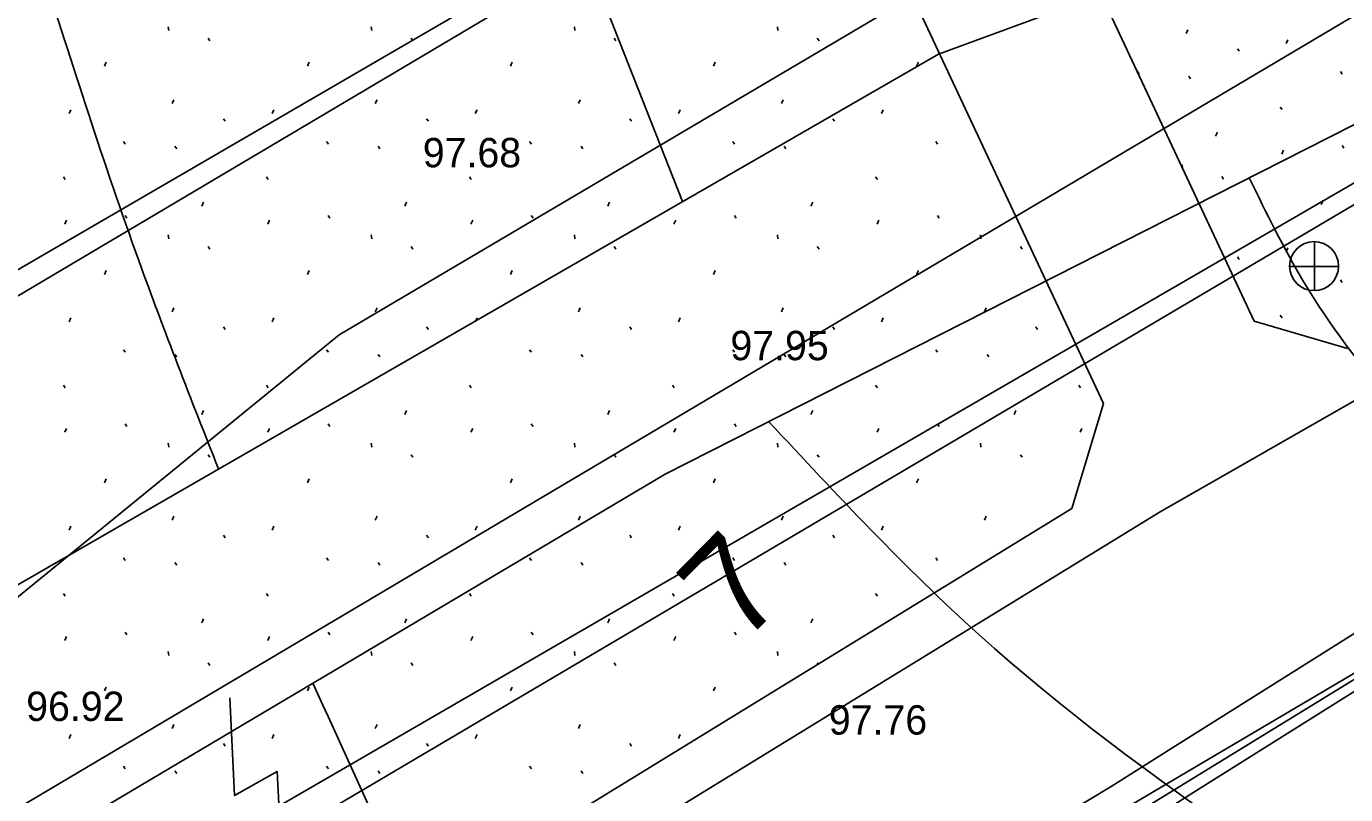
# Model space of a CAD drawing. Extents: x 412225 to 413380, y 4456471 to 4457189.
# Drawn here: x 412875.1 to 412929, y 4456690.9 to 4456722.3 of the extents above; entities that cross this region are included whole.
import ezdxf

# ---------------------------------------------------------------- set-up
doc = ezdxf.new("R2010")
doc.units = 0
for name, color, linetype in [('0_HALİHAZIR', 7, 'Continuous'), ('0_KADASTRO', 7, 'Continuous'), ('Level 28', 7, 'Continuous'), ('Level 41', 7, 'Continuous'), ('Level 54', 7, 'Continuous'), ('Level 62', 7, 'Continuous')]:
    doc.layers.add(name, color=color, linetype=linetype)

msp = doc.modelspace()

# ---------------------------------------------------------------- linework, layer by layer
at = {"layer": '0_HALİHAZIR'}
for p, q in [((412901.879, 4456715.112), (412894.207, 4456734.676)), ((412927.692, 4456711.466), (412927.692, 4456713.466)), ((412926.672, 4456712.456), (412928.672, 4456712.456))]:
    msp.add_line(p, q, dxfattribs=at)
for points in [[(413308.103, 4456965.941), (413265.175, 4456940.384), (413047.239, 4456812.664), (412821.475, 4456681.363)], [(412841.576, 4456665.003), (413057.926, 4456790.466), (413273.464, 4456916.652), (413307.769, 4456936.91)], [(412812.813, 4456662.398), (412856.245, 4456688.806), (412912.334, 4456721.138), (412944.097, 4456732.816)], [(412813.007, 4456650.071), (412835.489, 4456664.933), (412867.464, 4456683.962), (412901.181, 4456703.969), (412934.85, 4456721.065), (412956.754, 4456731.07), (412958.117, 4456731.459), (412959.035, 4456731.634), (412960.277, 4456731.39), (412961.32, 4456730.801), (412962.336, 4456729.858), (412972.363, 4456705.953), (412988.995, 4456670.284), (413003.917, 4456634.999), (413014.424, 4456609.495), (413014.707, 4456606.962), (413014.677, 4456605.697), (413014.483, 4456604.379), (413013.724, 4456603.316), (412984.218, 4456588.075)], [(412883.397, 4456694.839), (412883.59, 4456690.841), (412885.334, 4456691.821), (412885.53, 4456687.859)]]:
    msp.add_lwpolyline(points, dxfattribs=at)
msp.add_circle((412927.677, 4456712.475), 1, dxfattribs=at)
for points in [[(412882.93, 4456704.189), (412879.678, 4456712.699), (412875.677, 4456724.755)], [(412992.716, 4456661.485), (412992.328, 4456661.842), (412987.746, 4456666.132), (412977.092, 4456675.902), (412971.542, 4456680.769), (412970.43, 4456681.421), (412953.379, 4456688.33), (412947.814, 4456691.709), (412935.217, 4456702.348), (412927.264, 4456711.821), (412925.031, 4456716.079)], [(413005.761, 4456630.522), (413001.136, 4456632.263), (412984.376, 4456642.94), (412977.117, 4456647.694), (412971.593, 4456652.141), (412957.205, 4456665.099), (412943.851, 4456675.858), (412940.258, 4456678.239), (412939.048, 4456679.041), (412936.231, 4456681.076), (412913.981, 4456697.425), (412905.411, 4456706.117)], [(413011.724, 4456606.102), (412995.239, 4456621.045), (412991.947, 4456623.876), (412990.801, 4456624.547), (412958.936, 4456637.403), (412954.567, 4456639.817), (412938.594, 4456650.328), (412929.62, 4456655.175), (412907.019, 4456665.994), (412895.993, 4456677.467), (412894.135, 4456680.08), (412893.583, 4456681.1), (412886.792, 4456695.431)]]:
    msp.add_spline(points, degree=3, dxfattribs=at)
at = {"layer": '0_KADASTRO'}
for points in [[(412758.558, 4456668.786), (412808.977, 4456694.209), (412902.634, 4456741.974), (412909.074, 4456745.179), (412943.419, 4456762.272), (412949.024, 4456765.062), (412952.615, 4456766.849), (412963.581, 4456772.307), (412985.511, 4456783.221), (412985.536, 4456782.611), (412987.65, 4456731.4), (412981.45, 4456727.59), (412970.633, 4456720.947), (412967.171, 4456718.821), (412964.24, 4456717.02), (412920.19, 4456689.98), (412911.66, 4456684.75), (412892.499, 4456672.986), (412877.7, 4456663.9), (412867.363, 4456657.565), (412824.012, 4456630.971), (412807.183, 4456620.644)], [(412920.19, 4456689.98), (412964.24, 4456717.02), (412964.813, 4456715.755), (412986.81, 4456667.21), (412946.31, 4456645.15), (412920.457, 4456689.522)]]:
    msp.add_lwpolyline(points, close=True, dxfattribs=at)
at = {"layer": 'Level 28'}
for p, q in [((412925.229, 4456710.226), (412904.721, 4456754.025)), ((412905.602, 4456735.634), (412919.075, 4456706.861)), ((412922.99, 4456691.116), (412964.199, 4456717.067)), ((412929.039, 4456709.107), (412925.229, 4456710.226)), ((412919.075, 4456706.861), (412917.79, 4456702.575)), ((412917.79, 4456702.575), (412795.286, 4456627.414)), ((412920.449, 4456689.517), (412922.99, 4456691.117))]:
    msp.add_line(p, q, dxfattribs=at)
at = {"layer": 'Level 41'}
for p, q in [((412880.88, 4456722.26), (412880.898, 4456722.1)), ((412889.173, 4456722.26), (412889.191, 4456722.1)), ((412897.466, 4456722.26), (412897.484, 4456722.1)), ((412905.759, 4456722.26), (412905.777, 4456722.1)), ((412882.51, 4456721.79), (412882.58, 4456721.683)), ((412890.803, 4456721.79), (412890.873, 4456721.683)), ((412899.096, 4456721.79), (412899.166, 4456721.683)), ((412907.389, 4456721.79), (412907.459, 4456721.683)), ((412922.45, 4456721.975), (412922.52, 4456722.135)), ((412926.533, 4456721.567), (412926.604, 4456721.727)), ((412924.545, 4456721.359), (412924.616, 4456721.253)), ((412878.273, 4456720.646), (412878.345, 4456720.806)), ((412886.566, 4456720.646), (412886.638, 4456720.806)), ((412894.859, 4456720.646), (412894.931, 4456720.806)), ((412903.152, 4456720.646), (412903.224, 4456720.806)), ((412911.445, 4456720.646), (412911.517, 4456720.806)), ((412920.46, 4456720.43), (412920.531, 4456720.323)), ((412922.559, 4456720.238), (412922.63, 4456720.131)), ((412928.753, 4456720.43), (412928.824, 4456720.323)), ((412881.045, 4456719.116), (412881.115, 4456719.276)), ((412889.338, 4456719.116), (412889.408, 4456719.276)), ((412897.631, 4456719.116), (412897.701, 4456719.276)), ((412905.924, 4456719.116), (412905.994, 4456719.276)), ((412876.835, 4456718.708), (412876.906, 4456718.868)), ((412883.14, 4456718.5), (412883.211, 4456718.394)), ((412885.128, 4456718.708), (412885.199, 4456718.868)), ((412891.433, 4456718.5), (412891.504, 4456718.394)), ((412893.421, 4456718.708), (412893.492, 4456718.868)), ((412899.726, 4456718.5), (412899.797, 4456718.394)), ((412901.714, 4456718.708), (412901.785, 4456718.868)), ((412908.019, 4456718.5), (412908.09, 4456718.394)), ((412910.007, 4456718.708), (412910.078, 4456718.868)), ((412926.297, 4456718.977), (412926.368, 4456718.87)), ((412923.656, 4456717.784), (412923.727, 4456717.943)), ((412879.055, 4456717.571), (412879.126, 4456717.464)), ((412881.154, 4456717.379), (412881.225, 4456717.272)), ((412887.348, 4456717.571), (412887.419, 4456717.464)), ((412889.447, 4456717.379), (412889.518, 4456717.272)), ((412895.641, 4456717.571), (412895.712, 4456717.464)), ((412897.74, 4456717.379), (412897.811, 4456717.272)), ((412903.934, 4456717.571), (412904.005, 4456717.464)), ((412906.033, 4456717.379), (412906.104, 4456717.272)), ((412912.227, 4456717.571), (412912.298, 4456717.464)), ((412928.82, 4456717.4), (412928.891, 4456717.293)), ((412926.355, 4456717.055), (412926.427, 4456717.215)), ((412922.285, 4456716.609), (412922.299, 4456716.483)), ((412876.599, 4456716.118), (412876.67, 4456716.011)), ((412884.892, 4456716.118), (412884.963, 4456716.011)), ((412893.185, 4456716.118), (412893.256, 4456716.011)), ((412901.478, 4456716.118), (412901.549, 4456716.011)), ((412909.771, 4456716.118), (412909.842, 4456716.011)), ((412923.915, 4456716.139), (412923.985, 4456716.032)), ((412882.251, 4456714.925), (412882.322, 4456715.084)), ((412890.544, 4456714.925), (412890.615, 4456715.084)), ((412898.837, 4456714.925), (412898.908, 4456715.084)), ((412907.13, 4456714.925), (412907.201, 4456715.084)), ((412927.971, 4456714.995), (412928.043, 4456715.155)), ((412876.657, 4456714.196), (412876.729, 4456714.356)), ((412879.122, 4456714.541), (412879.193, 4456714.434)), ((412884.95, 4456714.196), (412885.022, 4456714.356)), ((412887.415, 4456714.541), (412887.486, 4456714.434)), ((412893.243, 4456714.196), (412893.315, 4456714.356)), ((412895.708, 4456714.541), (412895.779, 4456714.434)), ((412901.536, 4456714.196), (412901.608, 4456714.356)), ((412904.001, 4456714.541), (412904.072, 4456714.434)), ((412909.829, 4456714.196), (412909.901, 4456714.356)), ((412912.294, 4456714.541), (412912.365, 4456714.434)), ((412880.88, 4456713.75), (412880.898, 4456713.59)), ((412889.173, 4456713.75), (412889.191, 4456713.59)), ((412897.466, 4456713.75), (412897.484, 4456713.59)), ((412905.759, 4456713.75), (412905.777, 4456713.59)), ((412914.052, 4456713.75), (412914.07, 4456713.59)), ((412882.51, 4456713.28), (412882.58, 4456713.173)), ((412890.803, 4456713.28), (412890.873, 4456713.173)), ((412899.096, 4456713.28), (412899.166, 4456713.173)), ((412907.389, 4456713.28), (412907.459, 4456713.173)), ((412915.682, 4456713.28), (412915.752, 4456713.173)), ((412926.533, 4456713.057), (412926.604, 4456713.217)), ((412924.545, 4456712.849), (412924.616, 4456712.743)), ((412878.273, 4456712.136), (412878.345, 4456712.296)), ((412886.566, 4456712.136), (412886.638, 4456712.296)), ((412894.859, 4456712.136), (412894.931, 4456712.296)), ((412903.152, 4456712.136), (412903.224, 4456712.296)), ((412911.445, 4456712.136), (412911.517, 4456712.296)), ((412928.753, 4456711.92), (412928.824, 4456711.813)), ((412881.045, 4456710.606), (412881.115, 4456710.766)), ((412889.338, 4456710.606), (412889.408, 4456710.766)), ((412897.631, 4456710.606), (412897.701, 4456710.766)), ((412905.924, 4456710.606), (412905.994, 4456710.766)), ((412914.217, 4456710.606), (412914.287, 4456710.766)), ((412926.297, 4456710.467), (412926.368, 4456710.36)), ((412876.835, 4456710.198), (412876.906, 4456710.358)), ((412883.14, 4456709.99), (412883.211, 4456709.884)), ((412885.128, 4456710.198), (412885.199, 4456710.358)), ((412891.433, 4456709.99), (412891.504, 4456709.884)), ((412893.421, 4456710.198), (412893.492, 4456710.358)), ((412899.726, 4456709.99), (412899.797, 4456709.884)), ((412901.714, 4456710.198), (412901.785, 4456710.358)), ((412908.019, 4456709.99), (412908.09, 4456709.884)), ((412910.007, 4456710.198), (412910.078, 4456710.358)), ((412916.312, 4456709.99), (412916.383, 4456709.884)), ((412879.055, 4456709.061), (412879.126, 4456708.954)), ((412881.154, 4456708.869), (412881.225, 4456708.762)), ((412887.348, 4456709.061), (412887.419, 4456708.954)), ((412889.447, 4456708.869), (412889.518, 4456708.762)), ((412895.641, 4456709.061), (412895.712, 4456708.954)), ((412897.74, 4456708.869), (412897.811, 4456708.762)), ((412903.934, 4456709.061), (412904.005, 4456708.954)), ((412906.033, 4456708.869), (412906.104, 4456708.762)), ((412912.227, 4456709.061), (412912.298, 4456708.954)), ((412914.326, 4456708.869), (412914.397, 4456708.762)), ((412876.599, 4456707.608), (412876.67, 4456707.501)), ((412884.892, 4456707.608), (412884.963, 4456707.501)), ((412893.185, 4456707.608), (412893.256, 4456707.501)), ((412901.478, 4456707.608), (412901.549, 4456707.501)), ((412909.771, 4456707.608), (412909.842, 4456707.501)), ((412918.064, 4456707.608), (412918.135, 4456707.501)), ((412882.251, 4456706.415), (412882.322, 4456706.574)), ((412890.544, 4456706.415), (412890.615, 4456706.574)), ((412898.837, 4456706.415), (412898.908, 4456706.574)), ((412907.13, 4456706.415), (412907.201, 4456706.574)), ((412915.423, 4456706.415), (412915.494, 4456706.574)), ((412876.657, 4456705.686), (412876.729, 4456705.846)), ((412879.122, 4456706.031), (412879.193, 4456705.924)), ((412884.95, 4456705.686), (412885.022, 4456705.846)), ((412887.415, 4456706.031), (412887.486, 4456705.924)), ((412893.243, 4456705.686), (412893.315, 4456705.846)), ((412895.708, 4456706.031), (412895.779, 4456705.924)), ((412901.536, 4456705.686), (412901.608, 4456705.846)), ((412904.001, 4456706.031), (412904.072, 4456705.924)), ((412909.829, 4456705.686), (412909.901, 4456705.846)), ((412912.294, 4456706.031), (412912.365, 4456705.924)), ((412918.122, 4456705.686), (412918.194, 4456705.846)), ((412880.88, 4456705.24), (412880.898, 4456705.08)), ((412889.173, 4456705.24), (412889.191, 4456705.08)), ((412897.466, 4456705.24), (412897.484, 4456705.08)), ((412905.759, 4456705.24), (412905.777, 4456705.08)), ((412914.052, 4456705.24), (412914.07, 4456705.08)), ((412882.51, 4456704.77), (412882.58, 4456704.663)), ((412890.803, 4456704.77), (412890.873, 4456704.663)), ((412899.096, 4456704.77), (412899.166, 4456704.663)), ((412907.389, 4456704.77), (412907.459, 4456704.663)), ((412915.682, 4456704.77), (412915.752, 4456704.663)), ((412878.273, 4456703.626), (412878.345, 4456703.786)), ((412886.566, 4456703.626), (412886.638, 4456703.786)), ((412894.859, 4456703.626), (412894.931, 4456703.786)), ((412903.152, 4456703.626), (412903.224, 4456703.786)), ((412911.445, 4456703.626), (412911.517, 4456703.786)), ((412876.835, 4456701.688), (412876.906, 4456701.848)), ((412881.045, 4456702.096), (412881.115, 4456702.256)), ((412885.128, 4456701.688), (412885.199, 4456701.848)), ((412889.338, 4456702.096), (412889.408, 4456702.256)), ((412893.421, 4456701.688), (412893.492, 4456701.848)), ((412897.631, 4456702.096), (412897.701, 4456702.256)), ((412901.714, 4456701.688), (412901.785, 4456701.848)), ((412905.924, 4456702.096), (412905.994, 4456702.256)), ((412910.007, 4456701.688), (412910.078, 4456701.848)), ((412914.217, 4456702.096), (412914.287, 4456702.256)), ((412883.14, 4456701.48), (412883.211, 4456701.374)), ((412891.433, 4456701.48), (412891.504, 4456701.374)), ((412899.726, 4456701.48), (412899.797, 4456701.374)), ((412908.019, 4456701.48), (412908.09, 4456701.374)), ((412879.055, 4456700.551), (412879.126, 4456700.444)), ((412881.154, 4456700.359), (412881.225, 4456700.252)), ((412887.348, 4456700.551), (412887.419, 4456700.444)), ((412889.447, 4456700.359), (412889.518, 4456700.252)), ((412895.641, 4456700.551), (412895.712, 4456700.444)), ((412897.74, 4456700.359), (412897.811, 4456700.252)), ((412903.934, 4456700.551), (412904.005, 4456700.444)), ((412906.033, 4456700.359), (412906.104, 4456700.252)), ((412912.227, 4456700.551), (412912.298, 4456700.444)), ((412876.599, 4456699.098), (412876.67, 4456698.991)), ((412884.892, 4456699.098), (412884.963, 4456698.991)), ((412893.185, 4456699.098), (412893.256, 4456698.991)), ((412901.478, 4456699.098), (412901.549, 4456698.991)), ((412909.771, 4456699.098), (412909.842, 4456698.991)), ((412882.251, 4456697.905), (412882.322, 4456698.064)), ((412890.544, 4456697.905), (412890.615, 4456698.064)), ((412898.837, 4456697.905), (412898.908, 4456698.064)), ((412907.13, 4456697.905), (412907.201, 4456698.064)), ((412879.122, 4456697.521), (412879.193, 4456697.414)), ((412887.415, 4456697.521), (412887.486, 4456697.414)), ((412895.708, 4456697.521), (412895.779, 4456697.414)), ((412904.001, 4456697.521), (412904.072, 4456697.414)), ((412876.657, 4456697.176), (412876.729, 4456697.336)), ((412884.95, 4456697.176), (412885.022, 4456697.336)), ((412893.243, 4456697.176), (412893.315, 4456697.336)), ((412901.536, 4456697.176), (412901.608, 4456697.336)), ((412880.88, 4456696.73), (412880.898, 4456696.57)), ((412889.173, 4456696.73), (412889.191, 4456696.57)), ((412897.466, 4456696.73), (412897.484, 4456696.57)), ((412905.759, 4456696.73), (412905.777, 4456696.57)), ((412882.51, 4456696.26), (412882.58, 4456696.153)), ((412890.803, 4456696.26), (412890.873, 4456696.153)), ((412899.096, 4456696.26), (412899.166, 4456696.153)), ((412907.389, 4456696.26), (412907.42, 4456696.213)), ((412878.273, 4456695.116), (412878.345, 4456695.276)), ((412886.566, 4456695.116), (412886.638, 4456695.276)), ((412894.859, 4456695.116), (412894.931, 4456695.276)), ((412903.152, 4456695.116), (412903.224, 4456695.276)), ((412881.045, 4456693.586), (412881.115, 4456693.746)), ((412889.338, 4456693.586), (412889.408, 4456693.746)), ((412897.631, 4456693.586), (412897.701, 4456693.746)), ((412876.835, 4456693.178), (412876.906, 4456693.338)), ((412885.128, 4456693.178), (412885.199, 4456693.338)), ((412893.421, 4456693.178), (412893.492, 4456693.338)), ((412901.714, 4456693.178), (412901.785, 4456693.338)), ((412883.14, 4456692.97), (412883.211, 4456692.864)), ((412891.433, 4456692.97), (412891.504, 4456692.864)), ((412899.726, 4456692.97), (412899.797, 4456692.864)), ((412879.055, 4456692.041), (412879.126, 4456691.934)), ((412881.154, 4456691.849), (412881.225, 4456691.742)), ((412887.348, 4456692.041), (412887.419, 4456691.934)), ((412889.447, 4456691.849), (412889.518, 4456691.742)), ((412895.641, 4456692.041), (412895.712, 4456691.934)), ((412897.74, 4456691.849), (412897.811, 4456691.742))]:
    msp.add_line(p, q, dxfattribs=at)
at = {"layer": 'Level 54'}
msp.add_line((412839.084, 4456669.826), (412887.855, 4456709.671), dxfattribs=at)
for points in [[(412772.521, 4456650.705), (412780.988, 4456655.646), (413046.364, 4456813.097)], [(412842.641, 4456663.797), (413057.204, 4456790.554)], [(412887.855, 4456709.671), (412995.377, 4456773.192)], [(412856.216, 4456679.35), (412988.664, 4456757.933)], [(412904.619, 4456681.248), (413012.096, 4456744.742)]]:
    msp.add_lwpolyline(points, dxfattribs=at)
at = {"layer": 'Level 62'}
for p, q in [((412921.982, 4456692.846), (412965.981, 4456720.552)), ((412921.393, 4456702.44), (412930.105, 4456707.415)), ((412921.393, 4456702.44), (412819.706, 4456640.05)), ((412919.384, 4456691.21), (412921.982, 4456692.846)), ((412921.982, 4456692.846), (412921.982, 4456692.846)), ((412919.384, 4456691.21), (412910.874, 4456686.089))]:
    msp.add_line(p, q, dxfattribs=at)

# ---------------------------------------------------------------- texts
at = {"layer": '0_HALİHAZIR'}
for s, p in [('97.68', (412891.277, 4456716.514)), ('97.95', (412903.84, 4456708.631)), ('96.92', (412875.079, 4456693.889)), ('97.76', (412907.86, 4456693.332))]:
    msp.add_text(s, height=1.2, dxfattribs=at).set_placement(p)
at = {"layer": 'Level 54'}
msp.add_text('7', height=4, rotation=45.5609, dxfattribs=at).set_placement((412904.286, 4456696.943))

doc.saveas('drawing.dxf')
